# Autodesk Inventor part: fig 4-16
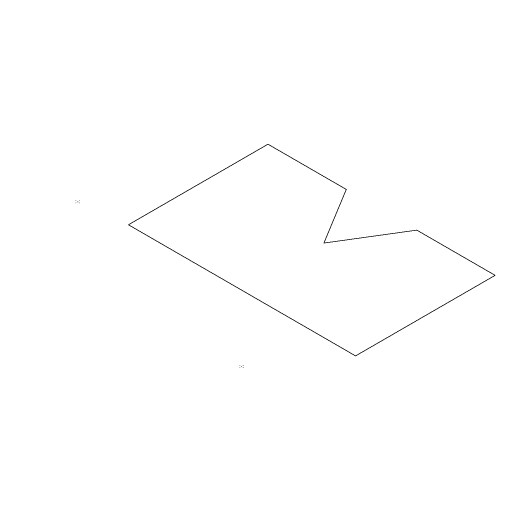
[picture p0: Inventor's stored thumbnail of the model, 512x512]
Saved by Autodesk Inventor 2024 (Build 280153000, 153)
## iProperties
Created: 2005-02
Part Number: fig 4-16
Document SubType Name: Modeling
Designer: CADCIM
Manufacturer: Standard
Standards Organization: Custom
Density: 1 g/cm^3
Material: Generic
Appearance: Default
Author: CADCIM
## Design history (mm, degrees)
sketch "Sketch1"
  geometry: L1 (-25.19, 27.524)-(-25.19, 5.557); L2 (-25.19, 5.557)-(10.567, 5.557); L3 (10.567, 5.557)-(10.567, 27.524); L4 (10.567, 27.524)-(-1.76, 27.524); L5 (-1.76, 27.524)-(-7.312, 18.449); L6 (-7.312, 18.449)-(-12.863, 27.524); L7 (-12.863, 27.524)-(-25.19, 27.524); 2 further points
  constraints: 14 end point, 3 equal length, 3 parallel, 1 perpendicular, 1 vertical, 1 other
